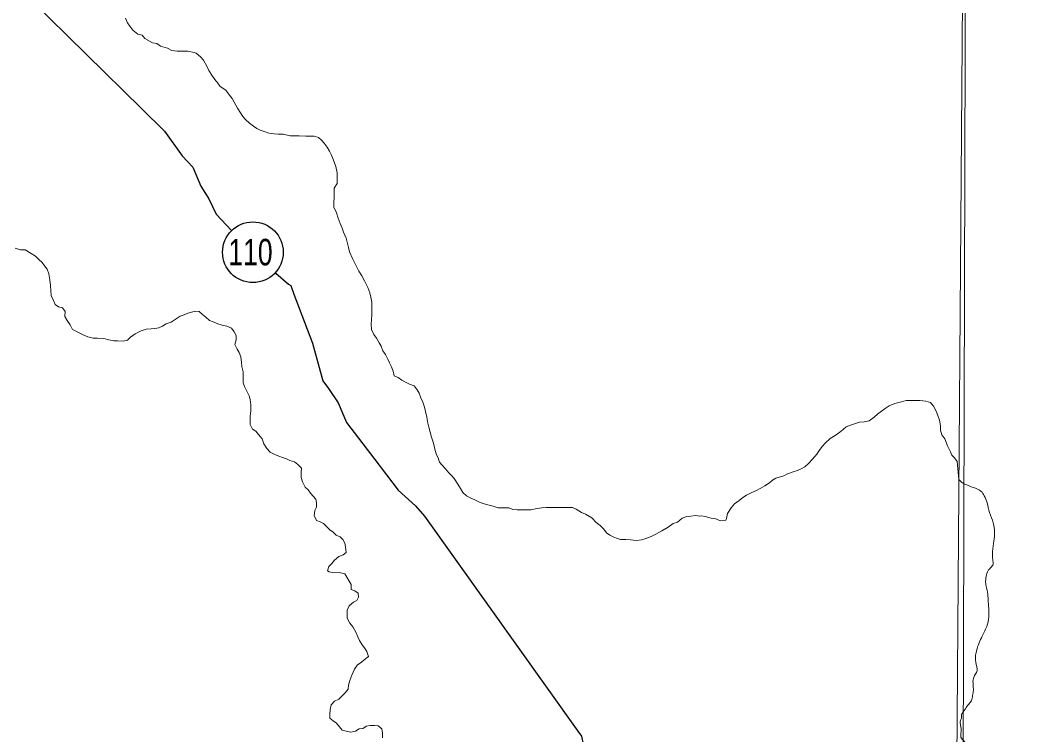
# Model space of a CAD drawing. Extents: x 553962 to 842807, y 8883888 to 9032388.
# Drawn here: x 616016 to 618663, y 8901086 to 8902976 of the extents above; entities that cross this region are included whole.
import ezdxf
from ezdxf.enums import TextEntityAlignment as Align

# ---------------------------------------------------------------- set-up
doc = ezdxf.new("R2010")
doc.units = 0
doc.header["$LTSCALE"] = 200
doc.layers.add('6', color=7, linetype='Continuous', lineweight=13)

msp = doc.modelspace()

# ---------------------------------------------------------------- linework, layer by layer
at = {"layer": '6'}
for points in [[(618663, 8924716.1), (618558.3, 8909803.7), (618456.5, 8896026.7)], [(616295.1, 8902981.4), (616301.1, 8902969.1), (616307.2, 8902959.9), (616315.2, 8902949.7), (616327.9, 8902939.1), (616339.5, 8902936.3), (616346.3, 8902927.4), (616366.4, 8902915.6), (616378.1, 8902914), (616388.1, 8902907.3)], [(616388.1, 8902907.3), (616406.5, 8902902.2), (616418.2, 8902895.6), (616431.6, 8902893.9), (616441.7, 8902893.9), (616460.1, 8902893.9), (616476.8, 8902890.5), (616482.6, 8902888.5), (616493.8, 8902879.2), (616501.8, 8902870), (616510.9, 8902852.7), (616515.9, 8902842.4), (616524, 8902830.2), (616532, 8902818.9), (616539.1, 8902809.7), (616546.1, 8902800.5), (616560.3, 8902791.2), (616570.4, 8902777.9), (616577.4, 8902768.7), (616582.5, 8902759.5), (616591.5, 8902743.1), (616599.6, 8902730.8), (616605.6, 8902721.6), (616612.7, 8902713.4), (616622.8, 8902703.2), (616633.9, 8902696), (616643, 8902689.8), (616651.3, 8902684.9), (616664.3, 8902680.5), (616674.5, 8902677.4), (616688.7, 8902675.3), (616698.9, 8902674.2), (616712.1, 8902674.1), (616730.4, 8902669.9), (616742.6, 8902669.8), (616754.8, 8902669.7), (616772.1, 8902669.6), (616784.3, 8902669.6), (616794.5, 8902669.5), (616805.6, 8902665.3), (616813.7, 8902658.2), (616820.8, 8902651), (616828.8, 8902639.7), (616834.9, 8902629.5), (616838.9, 8902620.3), (616844.9, 8902606), (616851.9, 8902588.6), (616854.8, 8902572.3), (616854.7, 8902555), (616854.6, 8902543.8), (616847.4, 8902531.6), (616847.3, 8902519.4), (616847.2, 8902508.2), (616846.1, 8902492.9), (616846.1, 8902481.7), (616853.1, 8902466.4), (616858.1, 8902452.1), (616863, 8902437.8), (616868, 8902425.5), (616872, 8902415.3), (616879.1, 8902399), (616882, 8902385.7), (616885, 8902374.5), (616888, 8902363.3), (616896, 8902345.9)], [(616003.4, 8902372.8), (616017.6, 8902368.7), (616029.8, 8902368.6), (616046, 8902359.3), (616057.2, 8902352.1), (616066.2, 8902342.9), (616075.3, 8902334.7), (616081.4, 8902326.5), (616088.5, 8902317.3), (616092.4, 8902305), (616095.4, 8902289.7), (616097.3, 8902274.4), (616098.2, 8902260.2), (616099.2, 8902247.9), (616105.2, 8902234.7), (616109.2, 8902224.4), (616118.3, 8902218.3), (616128.4, 8902215.2), (616135.5, 8902205.9), (616135.4, 8902192.7), (616141.4, 8902181.5), (616149.5, 8902170.2), (616155.5, 8902157.9), (616184.9, 8902142.5), (616196.1, 8902138.3), (616210.3, 8902135.2), (616221.5, 8902135.1), (616237.7, 8902134), (616250.9, 8902130.8), (616264.2, 8902127.7), (616274.3, 8902127.6), (616289.6, 8902127.5), (616300.8, 8902129.5), (616309, 8902137.6), (616321.2, 8902146.7), (616336.6, 8902154.7), (616349.8, 8902158.7), (616363, 8902159.7), (616373.2, 8902160.6), (616383.4, 8902162.6), (616393.6, 8902166.6), (616402.8, 8902172.7), (616416.1, 8902177.7), (616429.3, 8902185.7), (616439.6, 8902192.8), (616450.8, 8902196.8), (616460, 8902200.8), (616470.2, 8902203.8), (616480.3, 8902206.8), (616490.5, 8902205.7), (616498.6, 8902197.5), (616507.7, 8902190.3), (616517.8, 8902182.1), (616526.9, 8902178), (616539.1, 8902172.8), (616551.3, 8902169.7), (616563.5, 8902166.5), (616575.7, 8902161.3), (616582.7, 8902152.1), (616587.7, 8902141.9), (616587.7, 8902130.7), (616584.5, 8902118.5), (616590.5, 8902106.2), (616595.6, 8902097)], [(616896, 8902345.9), (616900, 8902336.7), (616905, 8902326.5), (616912, 8902312.2), (616920.1, 8902299.9), (616927.1, 8902286.6), (616936.1, 8902269.2), (616941.1, 8902254.9), (616944.1, 8902243.7), (616947.1, 8902230.4), (616947, 8902218.2), (616946.9, 8902207), (616946.8, 8902196.8), (616945.7, 8902184.6), (616944.6, 8902172.4), (616945.6, 8902158.1), (616951.6, 8902144.8), (616958.6, 8902134.6), (616965.7, 8902122.3), (616971.7, 8902114.1), (616975.7, 8902101.9), (616982.7, 8902091.7), (616988.8, 8902079.4), (616993.8, 8902070.2), (616997.8, 8902061), (617002.8, 8902047.7), (617005.7, 8902035.5), (617015.9, 8902031.3), (617026, 8902024.1), (617037.2, 8902018), (617046.3, 8902013.8), (617058.5, 8902008.7), (617066.5, 8901998.4), (617071.5, 8901989.2), (617076.5, 8901976.9), (617081.6, 8901965.7), (617085.5, 8901952.4)], [(616595.6, 8902097), (616600.6, 8902085.8), (616602.5, 8902070.5), (616603.4, 8902060.3), (616606.4, 8902046), (616606.3, 8902035.8), (616606.2, 8902016.5), (616610.2, 8902007.3), (616616.2, 8901995), (616622.2, 8901982.8), (616625.2, 8901972.6), (616627.2, 8901958.3), (616627.1, 8901943), (616624.9, 8901928.8), (616624.8, 8901917.6), (616624.8, 8901906.3), (616630.8, 8901894.1), (616639.9, 8901888.9), (616647, 8901880.7), (616657.1, 8901868.4), (616661, 8901855.2), (616669.1, 8901842.9), (616678.2, 8901833.7)], [(617882.8, 8901653.4), (617884.2, 8901658.2), (617887.4, 8901671.5), (617896.6, 8901686.7), (617905.8, 8901696.8), (617918.1, 8901705.9), (617927.3, 8901714), (617937.6, 8901720), (617951.8, 8901727.1), (617964.1, 8901732.1), (617973.3, 8901737.1), (617985.5, 8901744.2), (617997.8, 8901752.3), (618006, 8901759.3), (618015.2, 8901764.4), (618035.6, 8901771.4), (618045.8, 8901776.4), (618061.1, 8901781.4), (618072.3, 8901785.4), (618081.5, 8901789.4), (618091.7, 8901794.4), (618100.9, 8901803.6), (618112.2, 8901814.7), (618123.4, 8901827.9), (618129.6, 8901838), (618137.8, 8901849.2), (618145, 8901857.3), (618158.3, 8901869.4), (618171.6, 8901877.5), (618183.8, 8901886.6), (618193.1, 8901893.6), (618201.2, 8901900.7), (618212.5, 8901904.7), (618222.7, 8901908.7), (618235.9, 8901912.7), (618248.1, 8901913.7), (618261.4, 8901916.6), (618274.7, 8901925.7), (618283.9, 8901933.8), (618294.1, 8901941.9), (618304.3, 8901948.9), (618314.5, 8901956), (618329.8, 8901962), (618347.2, 8901967), (618359.4, 8901970), (618382.8, 8901969.8), (618396, 8901969.8), (618411.3, 8901968.6), (618423.4, 8901964.5), (618431.5, 8901955.3), (618438.5, 8901942), (618443.6, 8901930.7), (618447.5, 8901918.5), (618450.5, 8901903.2), (618450.4, 8901892), (618453.4, 8901879.7), (618461.4, 8901868.5), (618468.4, 8901850.1), (618476.5, 8901834.8), (618480.5, 8901825.6), (618487.5, 8901818.4), (618494.6, 8901809.2), (618499, 8901761.6)], [(617085.5, 8901952.4), (617088.5, 8901941.2), (617092.5, 8901925.9), (617094.4, 8901910.6), (617097.4, 8901899.4), (617101.3, 8901886.1), (617104.3, 8901872.9), (617109.3, 8901857.6), (617113.2, 8901841.2), (617117.2, 8901829), (617122.2, 8901817.7), (617125.2, 8901807.5), (617132.3, 8901799.3), (617141.4, 8901789.1), (617150.5, 8901778.8), (617157.5, 8901771.7), (617164.6, 8901763.5), (617173.7, 8901749.1), (617180.7, 8901737.9), (617187.7, 8901726.6), (617196.8, 8901718.4), (617208, 8901712.2), (617219.1, 8901707.1), (617229.3, 8901701.9), (617240.4, 8901697.8), (617256.7, 8901693.6), (617267.8, 8901690.5), (617281, 8901686.3), (617293.2, 8901686.2), (617308.5, 8901686.1), (617319.7, 8901682), (617330.8, 8901680.9), (617345.1, 8901680.8), (617355.3, 8901680.7), (617367.5, 8901680.7), (617383.8, 8901684.6), (617396, 8901686.6), (617407.2, 8901687.5), (617422.5, 8901687.4), (617437.7, 8901687.3), (617454, 8901687.2), (617464.2, 8901687.2), (617477.4, 8901687.1), (617486.5, 8901682.9), (617500.7, 8901673.7), (617511.8, 8901669.6), (617528.1, 8901660.3), (617540.2, 8901648), (617550.3, 8901639.8), (617560.4, 8901629.5), (617567.5, 8901620.3), (617575.6, 8901614.1), (617584.7, 8901610), (617593.8, 8901605.9), (617604, 8901602.7), (617618.2, 8901602.6), (617630.4, 8901601.6), (617646.7, 8901600.4), (617659.9, 8901601.4), (617671.1, 8901605.4), (617685.4, 8901610.4), (617697.6, 8901616.4), (617713, 8901625.5), (617730.3, 8901635.6), (617743.6, 8901644.6)], [(616678.2, 8901833.7), (616690.3, 8901827.5), (616700.5, 8901823.3), (616710.6, 8901819.2), (616720.8, 8901816.1), (616729.9, 8901811.9), (616742.1, 8901807.8), (616751.2, 8901800.6), (616760.3, 8901791.4), (616760.2, 8901780.2), (616760.1, 8901766.9), (616763.1, 8901754.7), (616770.1, 8901741.4), (616778.2, 8901734.2), (616784.2, 8901725), (616791.3, 8901716.8), (616798.4, 8901709.6), (616800.3, 8901699.4), (616800.3, 8901688.2), (616796.1, 8901679.1), (616794, 8901665.8), (616800, 8901652.6), (616810.2, 8901649.4), (616819.3, 8901645.3), (616826.4, 8901637.1), (616835.5, 8901627.9), (616844.6, 8901621.7), (616852.7, 8901614.5), (616862.8, 8901609.4), (616869.9, 8901602.2), (616874.9, 8901593), (616876.8, 8901582.8), (616878.8, 8901568.5), (616870.6, 8901562.5), (616859.4, 8901557.4), (616848.1, 8901548.3), (616840.9, 8901539.2), (616832.8, 8901531.1), (616829.6, 8901519.9), (616834.3, 8901517)], [(617743.6, 8901644.6), (617754.8, 8901648.6), (617767.1, 8901658.7), (617779.9, 8901663.6), (617790.1, 8901664.4), (617803.5, 8901666), (617813.7, 8901664.4), (617818.3, 8901665.2), (617827.8, 8901663.6), (617844.2, 8901658.9), (617856, 8901657.3), (617867.8, 8901651.8), (617882.8, 8901653.4)], [(616834.3, 8901517), (616847.9, 8901514.7), (616860.7, 8901515), (616874.9, 8901511.8), (616892, 8901483.2), (616891.9, 8901470), (616902.1, 8901466.8), (616910.2, 8901460.7), (616911.1, 8901450.5), (616907, 8901441.3), (616897.8, 8901437.3), (616886.6, 8901427.2), (616881.4, 8901416.1), (616881.3, 8901405.9), (616881.2, 8901394.7), (616888.3, 8901381.4), (616896.3, 8901372.1), (616905.4, 8901355.8), (616909.4, 8901345.6), (616914.4, 8901335.3), (616921.5, 8901324.1), (616927.5, 8901315.9), (616933.5, 8901306.7), (616937.5, 8901293.4), (616926.3, 8901284.3), (616918.1, 8901277.3), (616908.9, 8901271.2), (616900.7, 8901260.1), (616893.4, 8901243.8), (616888.2, 8901229.6), (616885.1, 8901217.4), (616884, 8901207.2), (616875.8, 8901197.1), (616867.6, 8901187.9), (616859.4, 8901180.8), (616848.2, 8901174.8), (616839, 8901165.7), (616836.9, 8901153.5), (616835.8, 8901140.2), (616835.7, 8901130.1), (616844.8, 8901122.9), (616852.9, 8901116.7), (616861, 8901107.5), (616868, 8901098.3), (616879.2, 8901096.2), (616891.4, 8901093), (616903.6, 8901096), (616912.8, 8901102.1), (616923, 8901103), (616932.2, 8901109.1), (616942.4, 8901111), (616953.6, 8901111), (616963.7, 8901109.9), (616972.8, 8901101.7), (616974.8, 8901090.5), (616974.7, 8901078.2)]]:
    msp.add_lwpolyline(points, dxfattribs=at)
msp.add_lwpolyline([(618535.2, 8909853.3), (607574.3, 8909890.7), (607543.3, 8898835.3), (618504.2, 8898795.8)], close=True, dxfattribs=at)
at = {"layer": '6', "lineweight": 25}
for points in [[(616044.3, 8903031.2), (616338.7, 8902741.3), (616398.6, 8902682.1), (616445.2, 8902616.8), (616473.6, 8902587.2), (616494.9, 8902537.3), (616516.1, 8902503.6), (616535.3, 8902462.8), (616575.3, 8902420.1)], [(616692.6, 8902307.3), (616726.2, 8902278.1), (616732.3, 8902274), (616740.4, 8902251.6), (616789.8, 8902122.1), (616817, 8902022.2), (616832.2, 8902001.8)], [(616832.2, 8902001.8), (616857.5, 8901964), (616879.7, 8901912), (616954.8, 8901814.1), (617016.6, 8901733.5), (617062.3, 8901691.6), (617085.6, 8901664.1), (617491.1, 8901095.8), (617501.2, 8901082.6), (617505.2, 8901061.2), (617519.8, 8900868.6), (617561, 8900712.6), (617580, 8900602.6), (617583.9, 8900553.7), (617583.7, 8900508.8), (617579.5, 8900483.4), (617569.1, 8900420.2), (617561.6, 8900327.5), (617544.5, 8899823.2), (617553.6, 8899807.9), (617563.8, 8899799.8), (617571, 8899793.8)]]:
    msp.add_lwpolyline(points, dxfattribs=at)
msp.add_circle((616632.2, 8902362.2), 80.3, dxfattribs=at)
at = {"layer": '6'}
msp.add_spline([(618499, 8901761.6), (618503.2, 8901756.5), (618514.3, 8901749.3), (618537.3, 8901740.1), (618557.5, 8901729.9), (618566, 8901718.5), (618573.2, 8901700), (618580, 8901674.2), (618589.5, 8901646.4), (618593.3, 8901621.8), (618591.2, 8901598.9), (618587.7, 8901571.1), (618588.4, 8901548.8), (618589.1, 8901537), (618583.5, 8901528.6), (618575.9, 8901520.3), (618571, 8901505), (618569.5, 8901492.9), (618571.1, 8901478.9), (618575.3, 8901458.1), (618576.3, 8901438.2), (618578.3, 8901414.3), (618577.9, 8901397.7), (618572.6, 8901372.7), (618558.5, 8901343), (618550.3, 8901324.2), (618544.1, 8901303.3), (618542.6, 8901289.4), (618545.9, 8901266.5), (618547.2, 8901256.2), (618542, 8901245.6), (618537.3, 8901235.3), (618536.4, 8901218.2), (618537.1, 8901203.9), (618535, 8901190.1), (618531.9, 8901176.4), (618524.9, 8901167.3), (618516, 8901155.2), (618510.6, 8901147.1), (618506.1, 8901139.1), (618505.3, 8901129.8), (618503, 8901122.9), (618503.4, 8901111.4), (618504.7, 8901093.6), (618504.2, 8901080), (618511.5, 8901070.3), (618519.3, 8901061), (618531.9, 8901048.2), (618539.3, 8901039.7), (618544.9, 8901022.6), (618545.9, 8901009.7), (618545.5, 8901001.1), (618542, 8900989.9), (618540.8, 8900979.8), (618540.4, 8900969.7)], degree=3, dxfattribs=at)

# ---------------------------------------------------------------- texts
at = {"layer": '6', "width": 0.75}
msp.add_text('110', height=70, dxfattribs=at).set_placement((616625.8, 8902327.6), align=Align.CENTER)

doc.saveas('drawing.dxf')
